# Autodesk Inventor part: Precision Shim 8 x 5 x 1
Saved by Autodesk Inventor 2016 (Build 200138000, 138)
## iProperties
Created: 2016-01
Part Number: Precision Shim 8 x 5 x 1
Material: Generic
Document SubType Name: Modeling
Designer: John
Density: 1 g/cm^3
Appearance: Default
Author: John
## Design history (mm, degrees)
feature "BOSS-EXTRUDE1"
body "Solid1"
